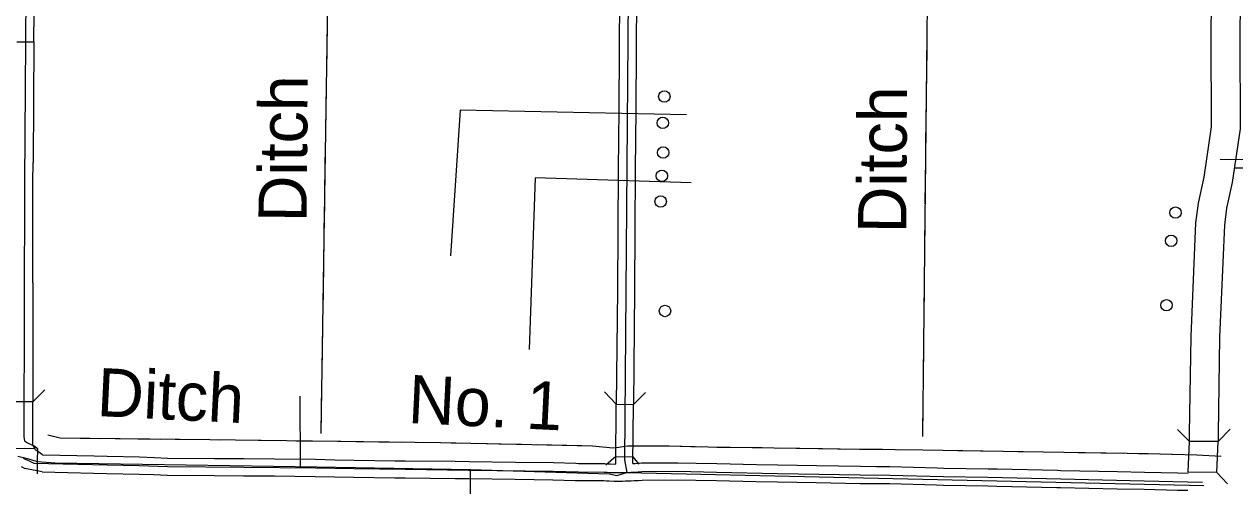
# Model space of a CAD drawing. Extents: x -4306 to 3843, y 131 to 8053.
# Drawn here: x -1949 to -251, y 221 to 879 of the extents above; entities that cross this region are included whole.
import ezdxf

# ---------------------------------------------------------------- set-up
doc = ezdxf.new("R2010")
doc.units = 0
for name, color, linetype in [('10', 7, 'Continuous'), ('31', 7, 'Continuous'), ('32', 7, 'Continuous'), ('35', 7, 'Continuous'), ('37', 7, 'Continuous'), ('38', 7, 'Continuous'), ('43', 7, 'Continuous'), ('56', 7, 'Continuous')]:
    doc.layers.add(name, color=color, linetype=linetype)

msp = doc.modelspace()

# ---------------------------------------------------------------- linework, layer by layer
at = {"layer": '10'}
for p, q in [((-316.2, 250.9), (-314.4, 293.8)), ((-274.4, 294), (-314.4, 293.9)), ((-276.2, 250.6), (-274.4, 293.9)), ((-276.2, 250.6), (-316.2, 250.9))]:
    msp.add_line(p, q, dxfattribs=at)
for points in [[(-314.4, 293.8), (-314.5, 305.1), (-312.3, 441.3), (-305.4, 600.9), (-302, 628.3), (-293.8, 664.7), (-283.6, 735.2), (-284.1, 861.9), (-282.2, 1054.1), (-278.9, 1201.3), (-280.3, 1434.8), (-278.7, 1599.9), (-273.4, 1758.6), (-274.2, 1917.6), (-271, 2305.4), (-270.3, 2716.6), (-269.9, 2753.7)], [(-229.9, 2753.2), (-230.3, 2716.3), (-231, 2305.2), (-234.2, 1917.5), (-233.4, 1758), (-238.7, 1599), (-240.3, 1434.8), (-238.9, 1200.9), (-242.2, 1053.5), (-244.1, 861.8), (-243.5, 732.4), (-254.4, 657.4), (-262.5, 621.4), (-265.5, 597.6), (-272.4, 440.2), (-274.5, 304.9), (-274.4, 293.9)]]:
    msp.add_lwpolyline(points, dxfattribs=at)
at = {"layer": '31'}
for p, q in [((-1959.7, 854.5), (-1935.7, 854.4)), ((-1935.7, 854.4), (-1936.3, 769.9)), ((-1936.3, 769.9), (-1936.9, 685.4)), ((-1936.9, 685.4), (-1936.9, 685.4)), ((-1937.4, 516.5), (-1937.5, 432)), ((-1937.5, 432), (-1937.5, 349.7)), ((-1937.5, 349.7), (-1961.5, 349.7)), ((-1937.5, 342.7), (-1937.5, 349.7)), ((-1937.5, 341), (-1937.5, 342.7)), ((-1937.5, 302), (-1937.5, 341)), ((-1937.3, 289), (-1937.5, 302)), ((-1933.7, 282.5), (-1937.3, 289)), ((-1934.5, 283.9), (-1961.5, 284)), ((-1923.6, 275.5), (-1933.7, 282.5))]:
    msp.add_line(p, q, dxfattribs=at)
for points in [[(-1935.7, 854.4), (-1935.1, 938.9)], [(-1937.2, 601), (-1937.1, 657.8), (-1936.9, 685.4)], [(-1937.4, 516.5), (-1937.2, 601)]]:
    msp.add_lwpolyline(points, dxfattribs=at)
at = {"layer": '32'}
for p, q in [((-1100.7, 1107.1), (-1107, 268.2)), ((-1114.1, 928.8), (-1114.7, 844.4)), ((-1090.1, 928.7), (-1090.7, 844.2)), ((-1114.7, 844.4), (-1115.3, 759.9)), ((-1090.7, 844.2), (-1091.3, 759.7)), ((-1115.3, 759.9), (-1116, 675.4)), ((-1091.3, 759.7), (-1092, 675.2)), ((-1116, 675.4), (-1116.6, 590.9)), ((-1092, 675.2), (-1092.6, 590.7)), ((-172.8, 677.2), (-251.5, 677.5)), ((-1116.6, 590.9), (-1117.2, 506.4)), ((-1092.6, 590.7), (-1093.2, 506.2)), ((-1117.2, 506.4), (-1118.7, 346.4)), ((-1093.2, 506.2), (-1094.7, 345.8)), ((-1562.5, 357.5), (-1562.4, 258.6)), ((-1119.3, 262.4), (-1118.7, 346.4)), ((-1118.7, 346.4), (-1094.7, 345.8)), ((-1095.3, 263.1), (-1094.7, 345.8)), ((-1958.3, 273.4), (-1944.6, 270.2)), ((-1923.6, 275.5), (-1851.4, 273.7)), ((-1851.4, 273.7), (-1832.8, 273.2)), ((-1832.8, 273.2), (-1787.5, 272.4)), ((-1787.5, 272.4), (-1766.7, 271.6)), ((-1119.2, 273.1), (-1095.2, 272.5)), ((-1953.5, 258.8), (-1948.3, 256.3)), ((-1950.7, 270.6), (-1948.8, 269.9)), ((-1948.8, 269.9), (-1944.7, 267.9)), ((-1924.4, 251.5), (-1948.3, 256.3)), ((-1944.7, 267.9), (-1942.2, 266.8)), ((-1944.6, 270.2), (-1931.4, 265.8)), ((-1942.2, 266.8), (-1936.1, 263.8)), ((-1936.1, 263.8), (-1833, 261.2)), ((-1931.4, 265.8), (-1905.9, 264)), ((-1905.9, 264), (-1538.4, 258.6)), ((-1833, 261.2), (-1787.9, 260.4)), ((-1787.9, 260.4), (-1748.4, 258.8)), ((-1766.7, 271.6), (-1748.2, 270.8)), ((-1748.4, 258.8), (-1641.2, 258)), ((-1748.2, 270.8), (-1682.6, 270.3)), ((-1682.6, 270.3), (-1641.1, 270)), ((-1641.2, 258), (-1540.8, 257.1)), ((-1641.1, 270), (-1598.1, 269.6)), ((-1598.1, 269.6), (-1540.7, 269.1)), ((-1540.8, 257.1), (-1486.7, 255.9)), ((-1540.7, 269.1), (-1513.5, 268.5)), ((-1538.4, 258.6), (-1323.2, 254.6)), ((-1513.5, 268.5), (-1486.5, 267.9)), ((-1486.7, 255.9), (-1414.9, 255)), ((-1486.5, 267.9), (-1429.1, 267.1)), ((-1429.1, 267.1), (-1414.8, 267)), ((-1414.9, 255), (-1325.5, 254)), ((-1414.8, 267), (-1344.7, 266.2)), ((-1344.7, 266.2), (-1325.3, 266)), ((-1325.3, 266), (-1260.2, 265.1)), ((-1260.2, 265.1), (-1207, 264.4)), ((-1207, 264.4), (-1175.5, 263.4)), ((-1175.5, 263.4), (-1171.6, 263.3)), ((-1171.6, 263.3), (-1135.1, 263.2)), ((-1135.1, 263.2), (-1130.4, 262.8)), ((-1130.4, 262.8), (-1127.4, 262.6)), ((-1127.4, 262.6), (-1119.3, 262.4)), ((-1107, 268.2), (-1103.8, 250.6)), ((-1095.3, 263.1), (-1092.1, 263.3)), ((-1092.1, 263.3), (-1089.4, 263.4)), ((-1089.4, 263.4), (-1083.2, 263.9)), ((-1083.2, 263.9), (-1032.4, 264.2)), ((-1032.4, 264.2), (-1006.7, 263.8)), ((-1006.7, 263.8), (-977.7, 263.2)), ((-977.7, 263.2), (-922.2, 261.9)), ((-922.2, 261.9), (-892.2, 261.2)), ((-892.2, 261.2), (-837.8, 260.3)), ((-837.8, 260.3), (-776.3, 259.3)), ((-776.3, 259.3), (-753.4, 259.1)), ((-753.4, 259.1), (-734.7, 258.9)), ((-734.7, 258.9), (-668.7, 257)), ((-668.7, 257), (-659.2, 256.7)), ((-659.2, 256.7), (-597, 255.8)), ((-597, 255.8), (-584.3, 255.5)), ((-584.3, 255.5), (-499.8, 253.6)), ((-1924.4, 251.5), (-1852, 249.7)), ((-1852, 249.7), (-1833.3, 249.2)), ((-1833.3, 249.2), (-1788.2, 248.4)), ((-1788.2, 248.4), (-1767.7, 247.6)), ((-1767.7, 247.6), (-1748.7, 246.8)), ((-1748.7, 246.8), (-1682.8, 246.3)), ((-1682.8, 246.3), (-1641.3, 246)), ((-1641.3, 246), (-1598.3, 245.6)), ((-1598.3, 245.6), (-1541, 245.1)), ((-1541, 245.1), (-1514, 244.5)), ((-1514, 244.5), (-1486.9, 243.9)), ((-1486.9, 243.9), (-1429.4, 243.1)), ((-1429.4, 243.1), (-1415.1, 243)), ((-1415.1, 243), (-1344.9, 242.2)), ((-1344.9, 242.2), (-1325.6, 242)), ((-1325.6, 242), (-1260.5, 241.1)), ((-1325.5, 254), (-1207.3, 252.4)), ((-1323.3, 220.7), (-1323.2, 254.6)), ((-1323.2, 254.6), (-1128.7, 248.6)), ((-1260.5, 241.1), (-1207.6, 240.4)), ((-1207.6, 240.4), (-1176.2, 239.4)), ((-1207.3, 252.4), (-1171.8, 251.3)), ((-1176.2, 239.4), (-1172, 239.3)), ((-1172, 239.3), (-1136.2, 239.2)), ((-1171.8, 251.3), (-1135.6, 251.2)), ((-1136.2, 239.2), (-1132.4, 238.9)), ((-1135.6, 251.2), (-1131.4, 250.8)), ((-1132.4, 238.9), (-1128.6, 238.6)), ((-1131.4, 250.8), (-1128, 250.6)), ((-1128.7, 248.6), (-1117.8, 246.4)), ((-1128.6, 238.6), (-1121.9, 238.5)), ((-1128, 250.6), (-1121.8, 250.5)), ((-1121.9, 238.5), (-1110, 238.5)), ((-1121.8, 250.5), (-1110.2, 250.5)), ((-1117.8, 246.4), (-1103.8, 250.6)), ((-1110.2, 250.5), (-1105.9, 250.6)), ((-1110, 238.5), (-1105.6, 238.6)), ((-1105.9, 250.6), (-1098.3, 250.9)), ((-1105.6, 238.6), (-1097.7, 238.9)), ((-1103.8, 250.6), (-294.3, 232.4)), ((-1098.3, 250.9), (-1094.4, 251.1)), ((-1097.7, 238.9), (-1093.6, 239.2)), ((-1094.4, 251.1), (-1088.6, 251.5)), ((-1093.6, 239.2), (-1090.7, 239.3)), ((-1090.7, 239.3), (-1087.8, 239.5)), ((-1088.6, 251.5), (-1082.7, 251.9)), ((-1087.8, 239.5), (-1082.2, 239.9)), ((-1082.7, 251.9), (-1032.5, 252.2)), ((-1082.2, 239.9), (-1032.6, 240.2)), ((-1032.6, 240.2), (-1007.2, 239.8)), ((-1032.5, 252.2), (-978, 251.2)), ((-1007.2, 239.8), (-978.2, 239.2)), ((-978.2, 239.2), (-922.8, 237.9)), ((-978, 251.2), (-892.4, 249.2)), ((-922.8, 237.9), (-892.7, 237.2)), ((-892.4, 249.2), (-776.5, 247.3)), ((-776.5, 247.3), (-735, 246.9)), ((-735, 246.9), (-659.4, 244.7)), ((-659.4, 244.7), (-597.3, 243.8)), ((-597.3, 243.8), (-495.1, 241.5)), ((-499.8, 253.6), (-494.8, 253.5)), ((-495.1, 241.5), (-378, 239)), ((-494.8, 253.5), (-415.4, 251.8)), ((-415.4, 251.8), (-377.8, 251)), ((-378, 239), (-296.2, 237.1)), ((-377.8, 251), (-330.9, 249.9)), ((-330.9, 249.9), (-316.4, 249.5)), ((-892.7, 237.2), (-838.2, 236.3)), ((-838.2, 236.3), (-776.6, 235.3)), ((-776.6, 235.3), (-753.6, 235.1)), ((-753.6, 235.1), (-735.2, 234.9)), ((-735.2, 234.9), (-669.4, 233)), ((-669.4, 233), (-659.7, 232.7)), ((-659.7, 232.7), (-597.5, 231.8)), ((-597.5, 231.8), (-584.9, 231.5)), ((-584.9, 231.5), (-500.4, 229.6)), ((-500.4, 229.6), (-495.4, 229.5)), ((-495.4, 229.5), (-415.9, 227.8)), ((-415.9, 227.8), (-378.3, 227)), ((-378.3, 227), (-331.5, 225.9)), ((-331.5, 225.9), (-316.8, 225.6))]:
    msp.add_line(p, q, dxfattribs=at)
for points in [[(-1927.2, 3133.3), (-1928.9, 2805.9), (-1937.5, 1957.3), (-1941.9, 1537.3), (-1945.9, 1118.2), (-1949.1, 657.8)], [(2052.2, 1131.5), (2052.1, 731.6), (2051.2, 728.2), (2048.7, 726.1), (1900.1, 653.4), (1410.3, 639.5), (1370.3, 641.2), (1252.7, 662.8), (1223, 668.4), (1168.4, 681.6), (1136.3, 683.4), (569.9, 686.2), (-271.6, 689.6)], [(-1949.1, 657.8), (-1949.8, 300.7), (-1949.1, 294.9), (-1944.6, 292.1), (-1938.5, 289.2), (-1934.7, 287.6), (-1930.8, 284.4), (-1931.4, 265.8), (-1931.3, 248.5)]]:
    msp.add_lwpolyline(points, dxfattribs=at)
at = {"layer": '35'}
for p, q in [((-1337.7, 758.7), (-1351.4, 554.6)), ((-1020, 752.3), (-1337.7, 758.7)), ((-1232.7, 663.9), (-1240.8, 423.1)), ((-1013.7, 656.9), (-1232.7, 663.9))]:
    msp.add_line(p, q, dxfattribs=at)
at = {"layer": '37'}
for p, q in [((-331.5, 310.8), (-314.4, 293.9)), ((-274.4, 294), (-257.5, 311.1)), ((-261.4, 234.8), (-276.2, 250.6))]:
    msp.add_line(p, q, dxfattribs=at)
at = {"layer": '38'}
for p, q in [((-1118.7, 346.4), (-1135.4, 363.6)), ((-1077.5, 362.6), (-1094.7, 345.8)), ((-1119.2, 273.1), (-1133.6, 260.9)), ((-1086.8, 262.4), (-1095.2, 272.5))]:
    msp.add_line(p, q, dxfattribs=at)
msp.add_lwpolyline([(-1920.5, 366.6), (-1937.5, 349.7)], dxfattribs=at)
at = {"layer": '43'}
for points in [[(-1521.8, 1099.7), (-1522.9, 972), (-1533.2, 305.2)], [(-680.6, 1081.4), (-689.1, 300.9)], [(-1524.4, 877.9), (-1525.3, 814.6)], [(-683.1, 859.6), (-683.7, 796.3)], [(-1525.7, 793.5), (-1526.6, 730.1)], [(-684, 775.1), (-684.7, 711.8)], [(-1527, 709), (-1527.9, 645.6)], [(-684.9, 690.7), (-685.6, 627.3)], [(-1528.3, 624.5), (-1528.8, 592.8)], [(-685.8, 606.2), (-686.2, 574.5)], [(-1528.8, 592.8), (-1529.2, 561.1)], [(-686.2, 574.5), (-686.5, 542.8)], [(-1529.6, 540), (-1530.5, 476.7)], [(-686.7, 521.7), (-687.4, 458.3)], [(-1530.9, 455.5), (-1531.8, 392.2)], [(-687.6, 437.2), (-688.3, 373.8)], [(-1532.2, 371.1), (-1533.1, 307.7)], [(-688.6, 352.7), (-689.1, 300.9)], [(-1843, 297.9), (-1898.8, 298.5), (-1916.2, 302.8)], [(-270, 272.8), (-304.3, 274.6), (-372.7, 276.6), (-519.6, 279), (-688.7, 281.9), (-804.7, 283.2), (-989.8, 286), (-1044.3, 287.5), (-1103, 287.5), (-1118.4, 285), (-1123.6, 284.8), (-1151.9, 287.5), (-1365.2, 292), (-1688.9, 296.2), (-1898.8, 298.5)], [(-1790.2, 297.3), (-1821.9, 297.7)], [(-1758.5, 297), (-1790.2, 297.3)], [(-1674.1, 296), (-1688.9, 296.2), (-1737.4, 296.7)], [(-1589.6, 294.9), (-1652.9, 295.7)], [(-1505.1, 293.8), (-1568.5, 294.6)], [(-1420.6, 292.7), (-1484, 293.6)], [(-1336.1, 291.4), (-1365.2, 292), (-1399.5, 292.5)], [(-1283.3, 290.3), (-1315, 291)], [(-1251.7, 289.6), (-1283.3, 290.3)], [(-1167.2, 287.8), (-1230.6, 289.2)], [(-998.6, 286.2), (-1044.3, 287.5), (-1061.9, 287.5)], [(-914.1, 284.9), (-977.5, 285.8)], [(-829.6, 283.6), (-893, 284.6)], [(-776.8, 282.9), (-804.7, 283.2), (-808.5, 283.3)], [(-745.1, 282.6), (-776.8, 282.9)], [(-660.7, 281.4), (-688.7, 281.9), (-724, 282.3)], [(-576.2, 279.9), (-639.5, 281.1)], [(-491.7, 278.5), (-519.6, 279), (-555.1, 279.6)], [(-407.2, 277.1), (-470.6, 278.2)], [(-322.8, 275.2), (-372.7, 276.6), (-386.1, 276.8)]]:
    msp.add_lwpolyline(points, dxfattribs=at)
at = {"layer": '56'}
for centre in [(-1051.3, 778), (-1053.5, 740.9), (-1052.9, 699.3), (-1054.7, 666.6), (-1056.4, 630.6), (-334.1, 615.1), (-340.2, 575.6), (-346.7, 485.1), (-1050.4, 477.1)]:
    msp.add_circle(centre, 8, dxfattribs=at)

# ---------------------------------------------------------------- texts
at = {"layer": '43'}
for s, rotation, p in [('Ditch', 89.5668, (-1553.2, 601.5)), ('Ditch', 89.7133, (-711.9, 586.1)), ('Ditch', 357.2006, (-1848.3, 329.8)), ('No. 1', 357.2006, (-1411.7, 320.1))]:
    msp.add_text(s, height=67.59, rotation=rotation, dxfattribs=at).set_placement(p)

doc.saveas('drawing.dxf')
